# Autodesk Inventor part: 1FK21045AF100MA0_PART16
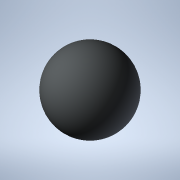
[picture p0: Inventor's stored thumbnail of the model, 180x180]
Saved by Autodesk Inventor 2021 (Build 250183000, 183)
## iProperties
Created: 2025-04
Part Number: 1FK21045AF100MA0_PART16
Material: Generic
Catalog Web Link: www.3dfindit.com
Description: -Servo synchronous motor
Document SubType Name: Modeling
Designer: psAdmin
Mass: 0.137258 g
Surface Area: 1.2868 cm^2
Volume: 0.137258 cm^3
Density: 1 g/cm^3
Appearance: PSOLRGB-212-217-219
Category: PARTsolutions
Title: 1FK21045AF100MA0_PART16
Author: Cadenas PARTsolutions
Comments: Servo synchronous motor
Sending System: PARTsolutions
Preprocessor: ST-DEVELOPER v19.3
PSOL_IDENT_0: {$CADENAS_DATA/23d-libs/siemens_ag/_cat_/52/6b/1fk21045af100ma0.prj},216 {VTYP=3D},{NB=1FK21045AF100
PSOL_IDENT_1: MA0_PART16},{LINA=1FK21045AF100MA0_PART16},{NN=1FK21045AF100MA0_PART16},{NOPRJ=TRUE},{DATE=19.08.202
PSOL_IDENT_2: 5 14:00:38},{GEOMDATE=30.07.2025 02:01:45},{VERSION=},{LINEID=10},{WBVAR=},{WBNUMERIC=}  {NB=1FK2104
PSOL_IDENT_3: 5AF100MA0_PART16},{LINA=1FK21045AF100MA0_PART16},{KT=DUMMY},{PREVIEW=../../../_pool_/cb/72/p_d211_xx
PSOL_IDENT_4: _00434j.png},{DESCSHORT=SIMOTICS S-1FK2 HD, SINAMICS S210 3AC 400V-480V, 2.4 Nm, 3000 rpm},{DESCLONG=
PSOL_IDENT_5: SIMOTICS S-1FK2 HD servo motor M0=2.4 Nm; PN = 0.75 kW at nN=3000 rpm (380-480 V); PN = 0.375 kW at
PSOL_IDENT_6: nN=1500 rpm (200-240 V); with holding brake; degree of protection IP64; cylindrical shaft D19x40mm;
PSOL_IDENT_7: absolute encoder 22-bit + 12-bit multiturn (encoder AM22DQC); with OCC interface; plug size M17, rot
PSOL_IDENT_8: atable; SIMOTICS S-1FK2 servomotorfor a wide range of uses in industrial environments. SIMOTICS S‑1F
PSOL_IDENT_9: K2 servomotors are compact synchronous motors with a high dynamic performance that set themselves ap
PSOL_IDENT_10: art as a result of their high power density, degree of protection and overload capability. The motor
PSOL_IDENT_11: s are available in two variants: as High Dynamic variant (highest dynamic performance as a result of
PSOL_IDENT_12: the low intrinsic moment of inertia for applications demanding a high dynamic performance with low
PSOL_IDENT_13: moved masses) - and as Compact variant (precise and stable closed-loop control for medium up to larg
PSOL_IDENT_14: e moved masses as a result of a medium intrinsic moment of inertia). SIMOTICSS‑1FK2 servomotors full
PSOL_IDENT_15: y exploit their strengths in a system with the SINAMICSS210 frequency converter and simple connectio
PSOL_IDENT_16: n using the one cable connection (OCC). Advantages include the short control and positioning times,
PSOL_IDENT_17: fast and precise correction of disturbing quantities as well as stable control with a high dynamic p
PSOL_IDENT_18: erformance. The servo motors can be configured to address a wide range of requirements. For example
PSOL_IDENT_19: with and without holding brake, IP64 or IP65 degree of protection, singleturn or multiturn absolute
PSOL_IDENT_20: encoders - to name just a few. Further, the servomotors are available in different shaft heights ext
PSOL_IDENT_21: ending from 20 to 100. A shaft sealing ring is available to achieve an IP65 degree of protection and
PSOL_IDENT_22: for subsequent mounting at the motor or as spare part. SIMOTICS - the optimum motor for each and ev
PSOL_IDENT_23: ery motion control application.},{INTNO=804766906411},{SUPPLIERALTNO=1FK2104-5AF10-0MA0},{MANUID=1FK
PSOL_IDENT_24: 21045AF100MA0},{MANUNAME=Siemens},{MANUTYPEDESC=Synchronous motor 1FK2-HD 2.4 NM},{AAU732=SIMOTICS},
PSOL_IDENT_25: {AAO057=S-1FK2},{AAU734=SIMOTICS S-1FK2 HD servo motor M0=2.4 Nm; PN = 0.75 kW at nN=3000 rpm (380-4
PSOL_IDENT_26: 80 V); PN = 0.375 kW at nN=1500 rpm (200-240 V); with holding brake; degree of protection IP64; cyli
PSOL_IDENT_27: ndrical shaft D19x40mm; absolute encoder 22-bit + 12-bit multiturn (encoder AM22DQC); with OCC inter
PSOL_IDENT_28: face; plug size M17, rotatable;},{AAW338=Synchronous motor 1FK2-HD 2.4 NM},{AAO742=SIMOTICS},{AAO663=
PSOL_IDENT_29: 4042948693070},{NOCUPEROU=1},{PRICEQUANTITY=1},{QUANTITYMIN=1},{QUANTITYINT=1},{CTN=85015100},{COO=D
PSOL_IDENT_30: E},{AAO676=1FK2104-5AF10-0MA0},{AAO677=Siemens AG},{ORDERUNIT=C62},{CONTENTUNIT=C62}
NB: 1FK21045AF100MA0_PART16
NT: Servo synchronous motor
NBSYN: $MANUID._PART16
LINA: 1FK21045AF100MA0_PART16
CATALOG: SIEMENS
PREVIEW: ../../../_pool_/cb/72/p_d211_xx_00434j.png
DESCSHORT: SIMOTICS S-1FK2 HD, SINAMICS S210 3AC 400V-480V, 2.4 Nm, 3000 rpm
DESCLONG: SIMOTICS S-1FK2 HD servo motor M0=2.4 Nm; PN = 0.75 kW at nN=3000 rpm (380-480 V); PN = 0.375 kW at nN=1500 rpm (200-240 V); with holding brake; degree of prote
INTNO: 804766906411
SUPPLIERALTNO: 1FK2104-5AF10-0MA0
MANUID: 1FK21045AF100MA0
MANUNAME: Siemens
MANUTYPEDESC: Synchronous motor 1FK2-HD 2.4 NM
AAU732: SIMOTICS
AAO057: S-1FK2
AAU734: SIMOTICS S-1FK2 HD servo motor M0=2.4 Nm; PN = 0.75 kW at nN=3000 rpm (380-480 V); PN = 0.375 kW at nN=1500 rpm (200-240 V); with holding brake; degree of prote
AAW338: Synchronous motor 1FK2-HD 2.4 NM
AAO742: SIMOTICS
AAO663: 4042948693070.0
NOCUPEROU: 1
PRICEQUANTITY: 1
QUANTITYMIN: 1
QUANTITYINT: 1
CTN: 85015100
COO: DE
ARTICLENO: 1FK21045AF100MA0_PART16
BOMINFO: 1FK21045AF100MA0_PART16
CREATOR: CADENAS GmbH
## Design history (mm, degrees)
feature "2025_04_17_15_34_52_0317"
body "Solid1"
